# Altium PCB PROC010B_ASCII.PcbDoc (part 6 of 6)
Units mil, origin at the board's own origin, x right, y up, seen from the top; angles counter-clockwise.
Board outline 3180 x 2565 mil, 6 copper layers (TOP, L2, L3, L4, L5, BOTTOM), stack 55.54 mil thick; 362 components, 264 nets, 1248 pads, 1144 vias.
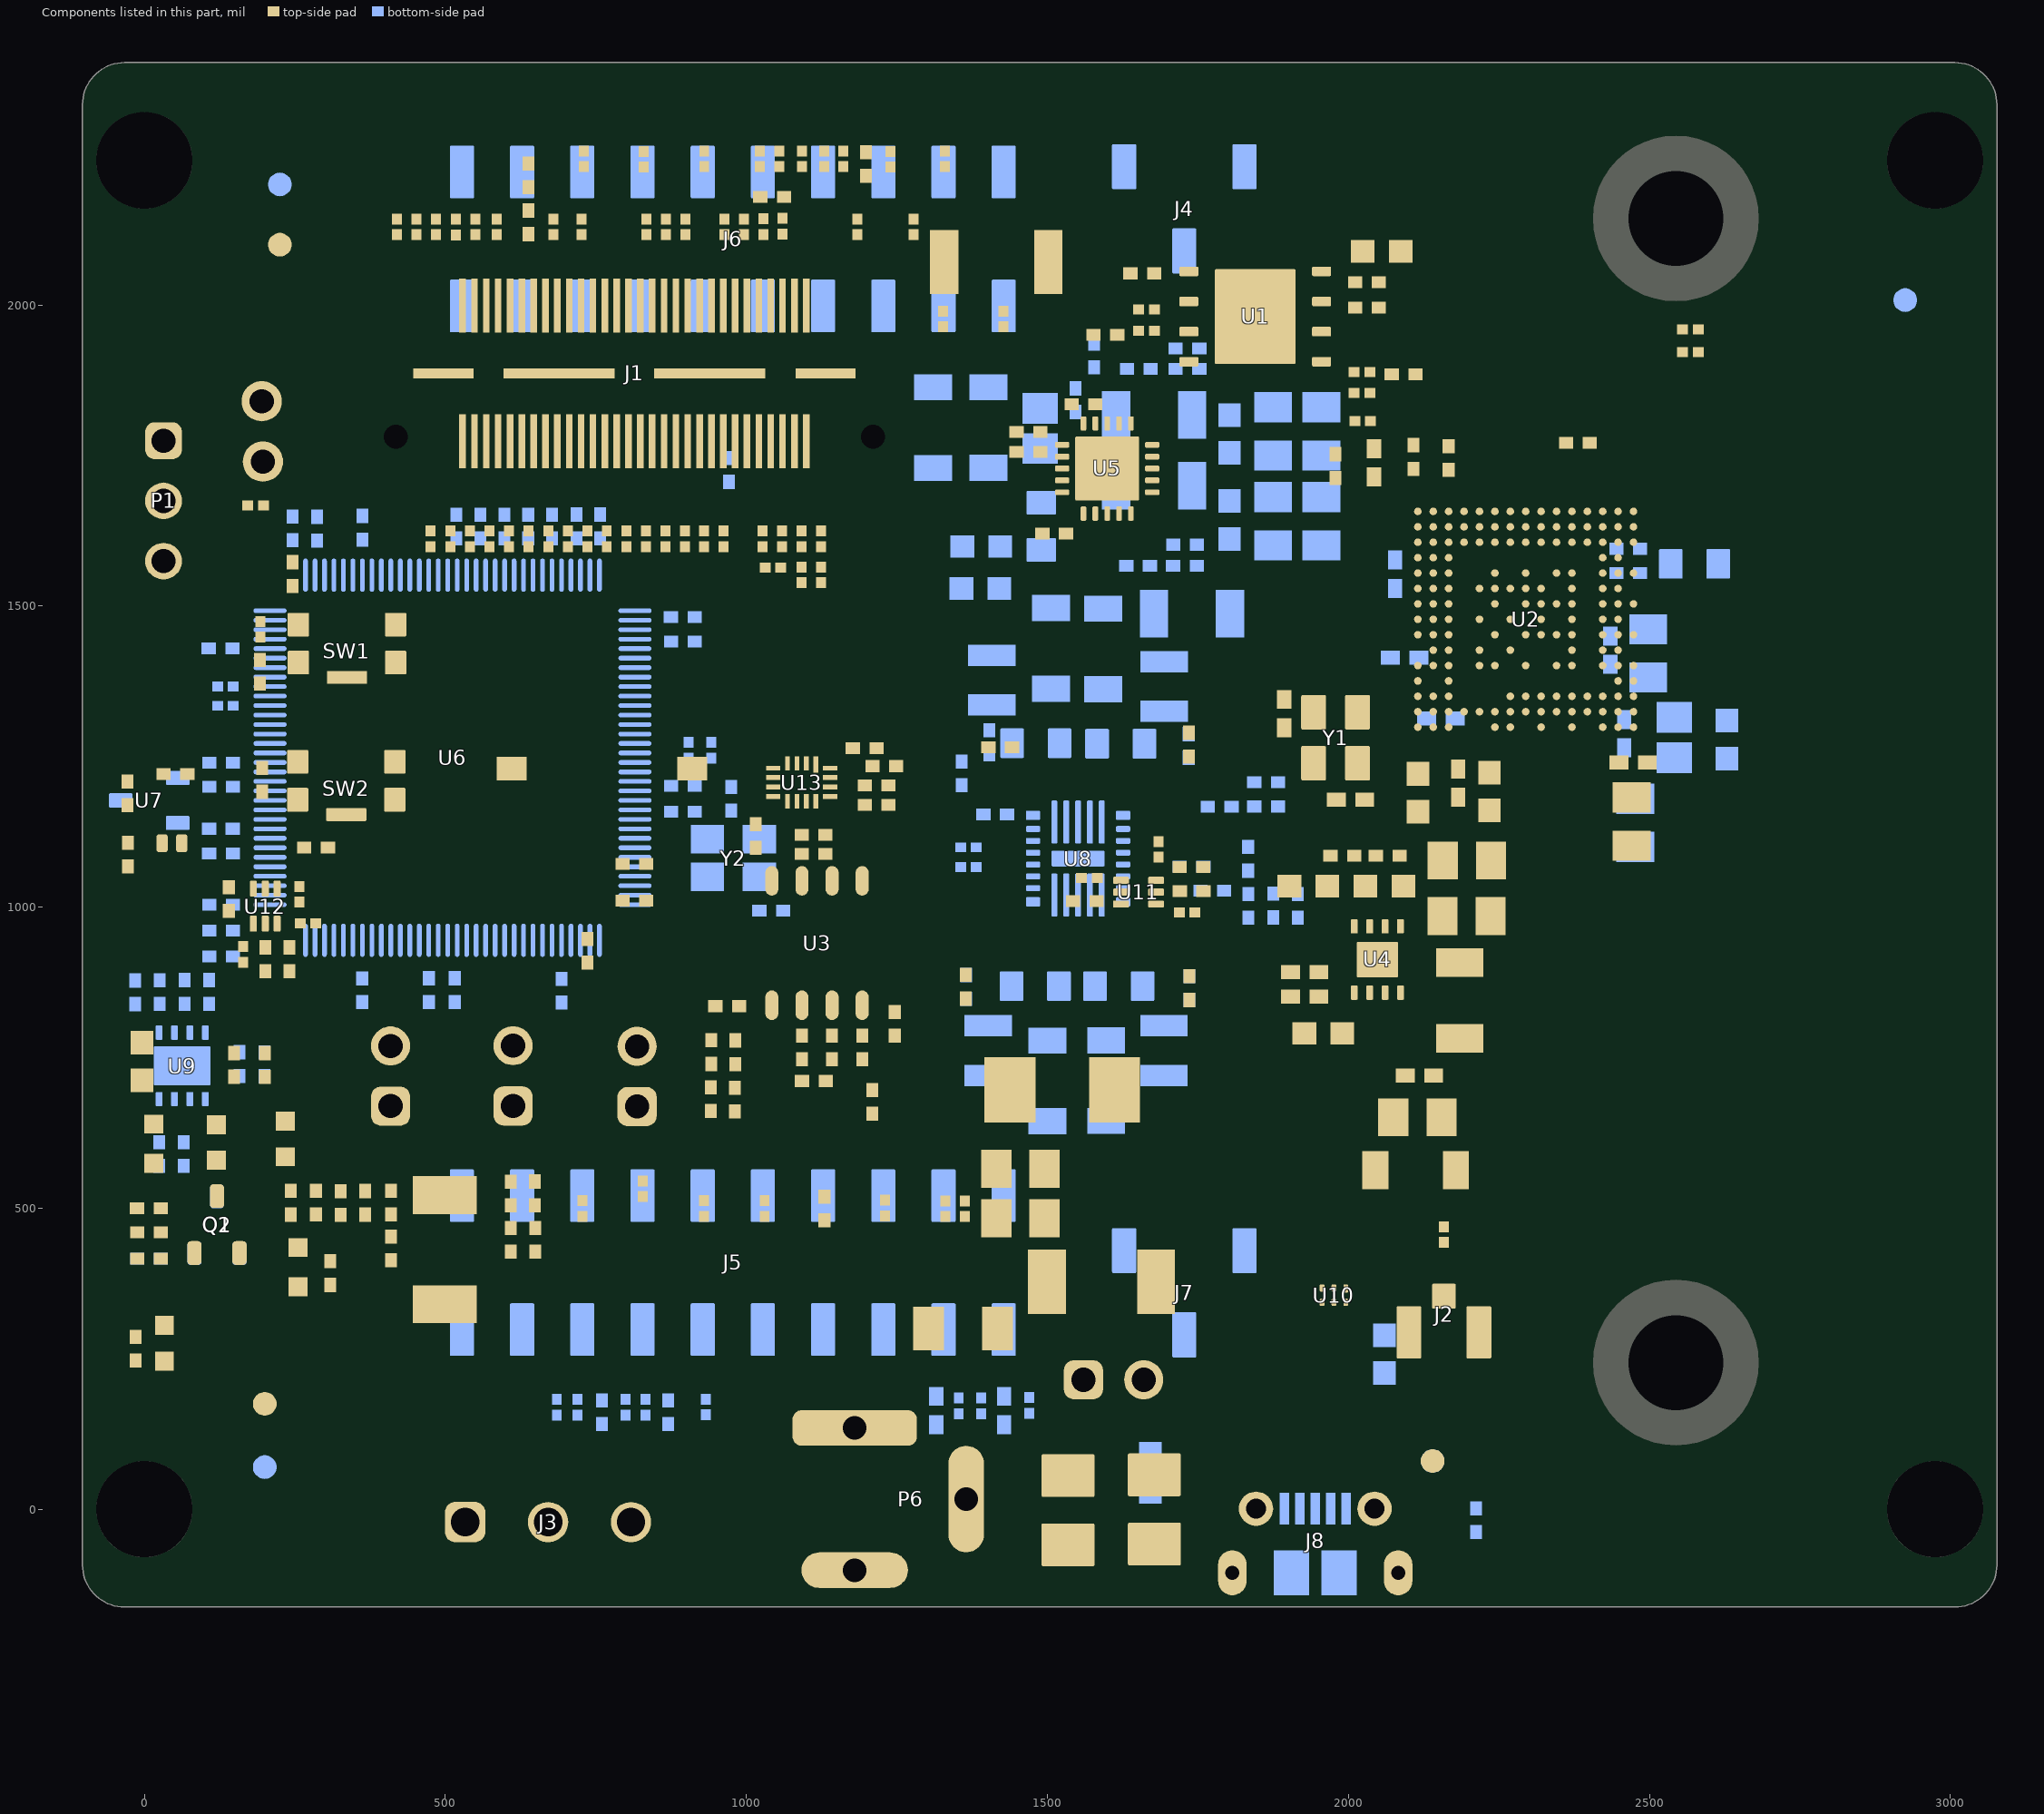
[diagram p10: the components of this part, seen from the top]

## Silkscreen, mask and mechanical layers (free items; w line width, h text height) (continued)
Drill Drawing:
  circle w9: c3144.49,3818.01 r27.78
  lines w9: 3116.71,3040.24 3172.27,3040.24 3172.27,3095.79 3116.71,3095.79 3116.71,3040.24 ; 3116.71,3970.79 3172.27,3970.79 3144.49,3915.24 3116.71,3970.79
  lines w10: 3066.68,3002.74 10059.06,3002.74 ; 3066.68,4502.74 10059.06,4502.74 ; 3067.25,4804.65 9682.22,4804.65 ; 3067.25,4929.65 9682.22,4929.65 ; 3150.75,5076.27 3884.08,5076.27 ; 3527.88,2877.74 3527.88,4627.74 ; 3528.44,4679.65 3528.44,5054.65 ; 4029.08,2877.74 4029.08,4627.74 ; 4029.64,4679.65 4029.64,5054.65 ; 4889.06,4679.65 4889.06,5054.65 ; 4988.46,2877.74 4988.46,4627.74 ; 5312.76,4679.65 5312.76,5054.65 ; 5412.16,2877.74 5412.16,4627.74 ; 5926.39,4679.65 5926.39,5054.65 ; 6025.79,2877.74 6025.79,4627.74 ; 6649.99,4679.65 6649.99,5054.65 ; 6985.18,2877.74 6985.18,4627.74 ; 7783.46,4679.65 7783.46,5054.65 ; 8118.65,2877.74 8118.65,4627.74 ; 8776.97,4679.65 8776.97,5054.65 ; 9112.16,2877.74 9112.16,4627.74 ; 3066.68,2877.74 10059.06,2877.74 10059.06,4627.74 3066.68,4627.74 3066.68,2877.74 ; 3067.25,4679.65 9682.22,4679.65 9682.22,5054.65 3067.25,5054.65 3067.25,4679.65
  text "DRILL CHART :" at 3150.16,5099.49 h60
  text "Symbol" at 3142.25,4967.15 h60
  text "Count" at 3565.94,4967.15 h60
  text "Hole Size" at 4067.14,4967.15 h60
  text "Plated" at 4926.56,4967.15 h60
  text "Hole Type" at 5350.26,4967.15 h60
  text "Hole Length" at 5963.89,4967.15 h60
  text "Routed Path Length" at 6687.49,4967.15 h60
  text "Drill Layer Pair" at 7820.96,4967.15 h60
  text "Tolerance" at 8814.47,4967.15 h60
  text "508" at 3565.94,4842.15 h50
  text "5.90mil (0.150mm)" at 4067.14,4842.15 h50
  text "PTH" at 4926.56,4842.15 h50
  text "Round" at 5350.26,4842.15 h50
  text "-" at 5963.89,4842.15 h50
  text "-" at 6687.49,4842.15 h50
  text "TOP - L2" at 7820.96,4842.15 h50
  text "+0.00mil/-5.90mil" at 8814.47,4842.15 h50
  text "A" at 3117.55,4833.16 h55.56
  text "508 Total" at 3565.94,4717.15 h50
  text "Symbol" at 3141.68,4540.24 h60
  text "Count" at 3565.38,4540.24 h60
  text "Hole Size" at 4066.58,4540.24 h60
  text "Plated" at 5025.96,4540.24 h60
  text "Hole Type" at 5449.66,4540.24 h60
  text "Hole Length" at 6063.29,4540.24 h60
  text "Routed Path Length" at 7022.68,4540.24 h60
  text "Drill Layer Pair" at 8156.15,4540.24 h60
  text "Hole Tolerance" at 9149.66,4540.24 h60
  text "15" at 3565.38,4415.24 h50
  text "7.87mil (0.200mm)" at 4066.58,4415.24 h50
  text "PTH" at 5025.96,4415.24 h50
  text "Round" at 5449.66,4415.24 h50
  text "-" at 6063.29,4415.24 h50
  text "-" at 7022.68,4415.24 h50
  text "TOP - BOTTOM" at 8156.15,4415.24 h50
  text "+0.00mil/-7.87mil" at 9149.66,4415.24 h50
  text "B" at 3116.98,4406.24 h55.56
  text "621" at 3565.38,4290.24 h50
  text "12.20mil (0.310mm)" at 4066.58,4290.24 h50
  text "PTH" at 5025.96,4290.24 h50
  text "Round" at 5449.66,4290.24 h50
  text "-" at 6063.29,4290.24 h50
  text "-" at 7022.68,4290.24 h50
  text "TOP - BOTTOM" at 8156.15,4290.24 h50
  text "+0.00mil/-12.20mil" at 9149.66,4290.24 h50
  text "C" at 3116.98,4281.24 h55.56
  text "2" at 3565.38,4165.24 h50
  text "23.62mil (0.600mm)" at 4066.58,4165.24 h50
  text "PTH" at 5025.96,4165.24 h50
  text "Slot" at 5449.66,4165.24 h50
  text "51.18mil (1.300mm)" at 6063.29,4165.24 h50
  text "27.56mil (0.700mm)" at 7022.68,4165.24 h50
  text "TOP - BOTTOM" at 8156.15,4165.24 h50
  text "+/-3.00mil" at 9149.66,4165.24 h50
  text "D" at 3116.98,4156.24 h55.56
  text "2" at 3565.38,4040.24 h50
  text "33.47mil (0.850mm)" at 4066.58,4040.24 h50
  text "PTH" at 5025.96,4040.24 h50
  text "Round" at 5449.66,4040.24 h50
  text "-" at 6063.29,4040.24 h50
  text "-" at 7022.68,4040.24 h50
  text "TOP - BOTTOM" at 8156.15,4040.24 h50
  text "+/-3.00mil" at 9149.66,4040.24 h50
  text "E" at 3116.98,4031.24 h55.56
  text "2" at 3565.38,3915.24 h50
  text "39.37mil (1.000mm)" at 4066.58,3915.24 h50
  text "PTH" at 5025.96,3915.24 h50
  text "Slot" at 5449.66,3915.24 h50
  text "118.11mil (3.000mm)" at 6063.29,3915.24 h50
  text "78.74mil (2.000mm)" at 7022.68,3915.24 h50
  text "TOP - BOTTOM" at 8156.15,3915.24 h50
  text "+/-3.00mil" at 9149.66,3915.24 h50
  text "1" at 3565.38,3790.24 h50
  text "39.37mil (1.000mm)" at 4066.58,3790.24 h50
  text "PTH" at 5025.96,3790.24 h50
  text "Slot" at 5449.66,3790.24 h50
  text "137.80mil (3.500mm)" at 6063.29,3790.24 h50
  text "98.43mil (2.500mm)" at 7022.68,3790.24 h50
  text "TOP - BOTTOM" at 8156.15,3790.24 h50
  text "+/-3.00mil" at 9149.66,3790.24 h50
  text "8" at 3565.38,3665.24 h50
  text "40.00mil (1.016mm)" at 4066.58,3665.24 h50
  text "PTH" at 5025.96,3665.24 h50
  text "Round" at 5449.66,3665.24 h50
  text "-" at 6063.29,3665.24 h50
  text "-" at 7022.68,3665.24 h50
  text "TOP - BOTTOM" at 8156.15,3665.24 h50
  text "+/-3.00mil" at 9149.66,3665.24 h50
  text "H" at 3116.98,3656.24 h55.56
  text "2" at 3565.38,3540.24 h50
  text "40.16mil (1.020mm)" at 4066.58,3540.24 h50
  text "NPTH" at 5025.96,3540.24 h50
  text "Round" at 5449.66,3540.24 h50
  text "-" at 6063.29,3540.24 h50
  text "-" at 7022.68,3540.24 h50
  text "TOP - BOTTOM" at 8156.15,3540.24 h50
  text "+/-2.00mil" at 9149.66,3540.24 h50
  text "J" at 3116.98,3531.24 h55.56
  text "5" at 3565.38,3415.24 h50
  text "40.16mil (1.020mm)" at 4066.58,3415.24 h50
  text "PTH" at 5025.96,3415.24 h50
  text "Round" at 5449.66,3415.24 h50
  text "-" at 6063.29,3415.24 h50
  text "-" at 7022.68,3415.24 h50
  text "TOP - BOTTOM" at 8156.15,3415.24 h50
  text "+/-3.00mil" at 9149.66,3415.24 h50
  text "I" at 3126.24,3406.24 h55.56
  text "3" at 3565.38,3290.24 h50
  text "47.24mil (1.200mm)" at 4066.58,3290.24 h50
  text "PTH" at 5025.96,3290.24 h50
  text "Round" at 5449.66,3290.24 h50
  text "-" at 6063.29,3290.24 h50
  text "-" at 7022.68,3290.24 h50
  text "TOP - BOTTOM" at 8156.15,3290.24 h50
  text "+/-3.00mil" at 9149.66,3290.24 h50
  text "K" at 3116.98,3281.24 h55.56
  text "2" at 3565.38,3165.24 h50
  text "157.48mil (4.000mm)" at 4066.58,3165.24 h50
  text "PTH" at 5025.96,3165.24 h50
  text "Round" at 5449.66,3165.24 h50
  text "-" at 6063.29,3165.24 h50
  text "-" at 7022.68,3165.24 h50
  text "TOP - BOTTOM" at 8156.15,3165.24 h50
  text "+/-3.00mil" at 9149.66,3165.24 h50
  text "L" at 3116.98,3156.24 h55.56
  text "4" at 3565.38,3040.24 h50
  text "160.00mil (4.064mm)" at 4066.58,3040.24 h50
  text "NPTH" at 5025.96,3040.24 h50
  text "Round" at 5449.66,3040.24 h50
  text "-" at 6063.29,3040.24 h50
  text "-" at 7022.68,3040.24 h50
  text "TOP - BOTTOM" at 8156.15,3040.24 h50
  text "+/-2.00mil" at 9149.66,3040.24 h50
  text "667 Total" at 3565.38,2915.24 h50
  text "Slot definitions :" at 3141.68,2793.09 h50
  text "Routed Path Length" at 4004.12,2793.09 h50
  text "= Calculated from tool start centre position to tool end centre position." at 4924.88,2793.09 h50
  text "Hole Length" at 4004.12,2708.45 h50
  text "= Routed Path Length + Tool Size = Slot length as defined in the PCB layout" at 4583.32,2708.45 h50
  text "FAB" at -523,-1458.49 h60
M17 Embedded Cavity:
  text ".Layer_Name" at -523,-1458.49 h60
M18 Embedded Assembly:
  text ".Layer_Name" at -523,-1458.49 h60
M19 Embedded Keepout:
  text ".Layer_Name" at -523,-1458.49 h60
